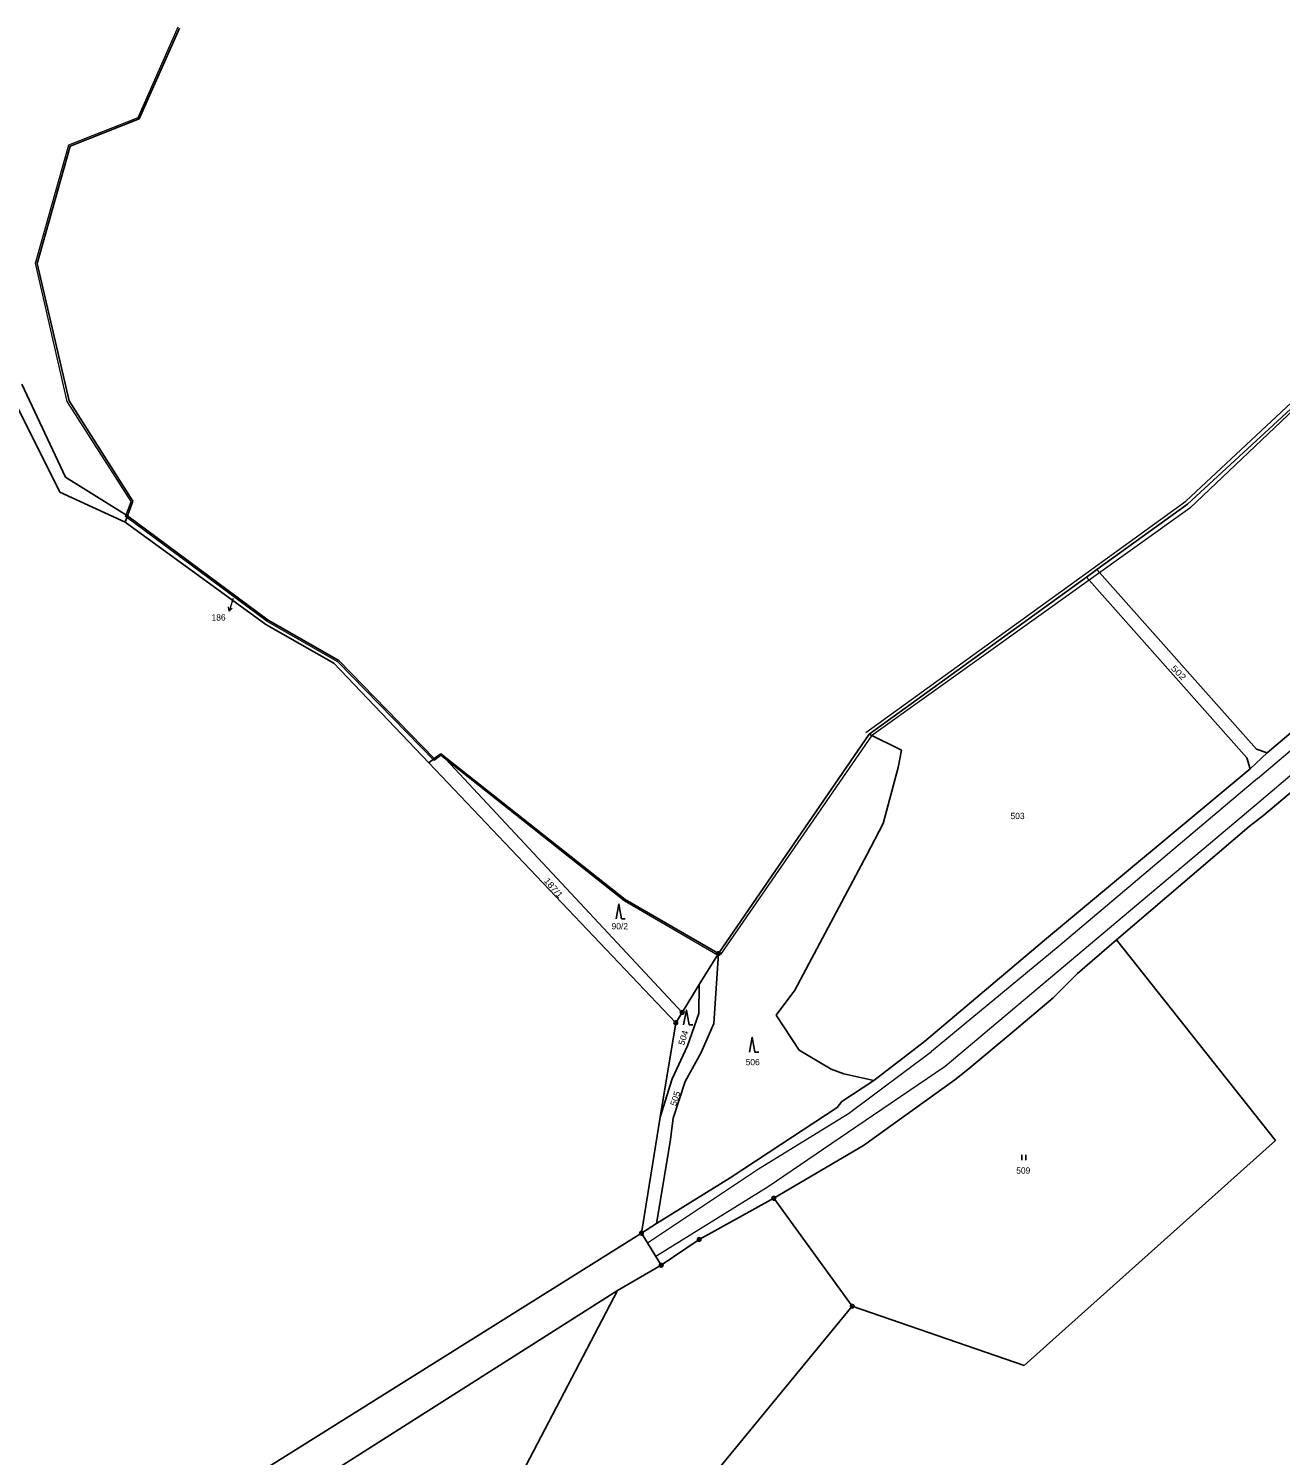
# Model space of a CAD drawing. Extents: x -653193 to -651624, y -1092017 to -1090260.
# Drawn here: x -652620.8 to -652283.1, y -1090861.4 to -1090476.3 of the extents above; entities that cross this region are included whole.
import ezdxf
from ezdxf.enums import TextEntityAlignment as Align

# ---------------------------------------------------------------- set-up
doc = ezdxf.new("R2010")
doc.units = 0
doc.header["$LTSCALE"] = 0.68
for name, color, linetype, lineweight in [('1', 7, 'Continuous', 25), ('3', 7, 'Continuous', 25), ('4', 7, 'Continuous', 13), ('7', 7, 'Continuous', 13), ('8', 7, 'Continuous', 25)]:
    doc.layers.add(name, color=color, linetype=linetype, lineweight=lineweight)
doc.layers.add('2', color=7, linetype='Continuous')

msp = doc.modelspace()

# ---------------------------------------------------------------- linework, layer by layer
at = {"layer": '1'}
for p, q in [((-652590.93, -1090500.73), (-652580.08, -1090476.22)), ((-652609.54, -1090508.04), (-652590.93, -1090500.73)), ((-652618.44, -1090539.69), (-652609.54, -1090508.04)), ((-652609.87, -1090576.8), (-652618.44, -1090539.69)), ((-652610.85, -1090597.36), (-652622.63, -1090572.26)), ((-652612.33, -1090601.42), (-652625.22, -1090575.6)), ((-652592.64, -1090603.89), (-652609.87, -1090576.8)), ((-652278.07, -1090576.84), (-652308.16, -1090604.7)), ((-652594.13, -1090607.87), (-652610.85, -1090597.36)), ((-652594.73, -1090609.56), (-652612.33, -1090601.42)), ((-652592.64, -1090603.89), (-652593.64, -1090606.57)), ((-652308.16, -1090604.7), (-652332.59, -1090622.35)), ((-652594.13, -1090607.87), (-652594.73, -1090609.56)), ((-652593.64, -1090606.57), (-652594.13, -1090607.87)), ((-652556.15, -1090635.96), (-652594.13, -1090607.87)), ((-652556.74, -1090637.15), (-652594.73, -1090609.56)), ((-652335.44, -1090624.41), (-652394.05, -1090666.77)), ((-652334.01, -1090623.38), (-652335.44, -1090624.41)), ((-652292.13, -1090673.13), (-652335.44, -1090624.41)), ((-652332.59, -1090622.35), (-652334.01, -1090623.38)), ((-652332.59, -1090622.35), (-652289.51, -1090670.8)), ((-652286.71, -1090671.78), (-652233.17, -1090626.65)), ((-652537.08, -1090646.85), (-652556.15, -1090635.96)), ((-652538.43, -1090647.58), (-652556.74, -1090637.15)), ((-652512.85, -1090674.5), (-652538.43, -1090647.58)), ((-652511.37, -1090673.36), (-652537.08, -1090646.85)), ((-652237.99, -1090646.81), (-652287.6, -1090688.58)), ((-652394.05, -1090666.77), (-652434.67, -1090725.95)), ((-652394.05, -1090666.77), (-652385.27, -1090671.07)), ((-652289.51, -1090670.8), (-652286.71, -1090671.78)), ((-652511.37, -1090673.36), (-652512.85, -1090674.5)), ((-652512.85, -1090674.5), (-652446.21, -1090744.64)), ((-652509.59, -1090672.03), (-652511.37, -1090673.36)), ((-652459.81, -1090711.37), (-652509.59, -1090672.03)), ((-652444.47, -1090741.83), (-652509.59, -1090672.03)), ((-652385.27, -1090671.07), (-652386.16, -1090675.71)), ((-652291.21, -1090676.12), (-652292.13, -1090673.13)), ((-652291.21, -1090676.12), (-652286.71, -1090671.78)), ((-652386.16, -1090675.71), (-652390.28, -1090690.83)), ((-652346.23, -1090721.9), (-652291.21, -1090676.12)), ((-652287.6, -1090688.58), (-652291.53, -1090691.65)), ((-652394.62, -1090699.31), (-652390.28, -1090690.83)), ((-652291.53, -1090691.65), (-652327.3, -1090722.23)), ((-652394.62, -1090699.31), (-652414.04, -1090735.86)), ((-652434.67, -1090725.95), (-652459.81, -1090711.37)), ((-652379.14, -1090749.72), (-652346.23, -1090721.9)), ((-652327.3, -1090722.23), (-652337.84, -1090731.35)), ((-652327.3, -1090722.23), (-652284.44, -1090776.42)), ((-652439.85, -1090734.34), (-652434.67, -1090725.95)), ((-652434.67, -1090725.95), (-652435.94, -1090744.83)), ((-652337.84, -1090731.35), (-652344.38, -1090737.91)), ((-652444.47, -1090741.83), (-652439.85, -1090734.34)), ((-652439.99, -1090742.13), (-652439.85, -1090734.34)), ((-652414.04, -1090735.86), (-652419.07, -1090742.55)), ((-652344.38, -1090737.91), (-652355.48, -1090747.23)), ((-652446.21, -1090744.64), (-652444.47, -1090741.83)), ((-652443.03, -1090750.89), (-652439.99, -1090742.13)), ((-652419.07, -1090742.55), (-652412.93, -1090752.06)), ((-652450.37, -1090770.15), (-652446.21, -1090744.64)), ((-652435.94, -1090744.83), (-652439.31, -1090752.66)), ((-652355.48, -1090747.23), (-652367.4, -1090757.27)), ((-652447.18, -1090759.75), (-652443.03, -1090750.89)), ((-652392.75, -1090760.24), (-652379.14, -1090749.72)), ((-652439.31, -1090752.66), (-652443.67, -1090760.48)), ((-652412.93, -1090752.06), (-652404.29, -1090757.12)), ((-652404.29, -1090757.12), (-652400.9, -1090758.45)), ((-652400.9, -1090758.45), (-652392.75, -1090760.24)), ((-652367.4, -1090757.27), (-652370.91, -1090760.03)), ((-652450.37, -1090770.15), (-652447.18, -1090759.75)), ((-652443.67, -1090760.48), (-652446.86, -1090770.38)), ((-652401.43, -1090765.9), (-652392.75, -1090760.24)), ((-652370.91, -1090760.03), (-652395.6, -1090777.78)), ((-652402.66, -1090767.49), (-652401.43, -1090765.9)), ((-652455.47, -1090801.44), (-652450.37, -1090770.15)), ((-652446.86, -1090770.38), (-652447.71, -1090776.73)), ((-652417.82, -1090777.48), (-652402.66, -1090767.49)), ((-652447.71, -1090776.73), (-652451.39, -1090798.77)), ((-652431.48, -1090786.52), (-652417.82, -1090777.48)), ((-652395.6, -1090777.78), (-652419.75, -1090792)), ((-652284.44, -1090776.42), (-652352.22, -1090837.11)), ((-652451.39, -1090798.77), (-652431.48, -1090786.52)), ((-652419.75, -1090792), (-652439.86, -1090803.1)), ((-652398.57, -1090821.14), (-652419.75, -1090792)), ((-652587.98, -1090884.44), (-652455.47, -1090801.44)), ((-652455.47, -1090801.44), (-652451.39, -1090798.77)), ((-652453.86, -1090804.03), (-652455.47, -1090801.44)), ((-652451.55, -1090807.75), (-652453.86, -1090804.03)), ((-652439.86, -1090803.1), (-652450.11, -1090810.08)), ((-652450.11, -1090810.08), (-652451.55, -1090807.75)), ((-652461.88, -1090816.92), (-652450.11, -1090810.08)), ((-652590.07, -1090898.28), (-652461.88, -1090816.92)), ((-652547.89, -1090980.88), (-652461.88, -1090816.92)), ((-652440.11, -1090871.57), (-652398.57, -1090821.14)), ((-652352.22, -1090837.11), (-652398.57, -1090821.14))]:
    msp.add_line(p, q, dxfattribs=at)
at = {"layer": '3'}
for p, q in [((-652460.8, -1090716.6), (-652459.804, -1090716.6)), ((-652442.58, -1090745.21), (-652441.584, -1090745.21)), ((-652424.83, -1090752.53), (-652423.834, -1090752.53)), ((-652352.801, -1090781.74), (-652352.801, -1090780.24)), ((-652351.8, -1090781.74), (-652351.8, -1090780.24))]:
    msp.add_line(p, q, dxfattribs=at)
for points in [[(-652460.8, -1090716.6), (-652461.55, -1090712.6), (-652462.3, -1090716.6)], [(-652442.58, -1090745.21), (-652443.33, -1090741.21), (-652444.08, -1090745.21)], [(-652424.83, -1090752.53), (-652425.58, -1090748.53), (-652426.33, -1090752.53)]]:
    msp.add_lwpolyline(points, dxfattribs=at)
at = {"layer": '4'}
for p, q in [((-652591.23, -1090500.33), (-652580.44, -1090475.87)), ((-652609.93, -1090507.73), (-652591.23, -1090500.33)), ((-652618.94, -1090539.65), (-652609.93, -1090507.73)), ((-652610.33, -1090576.99), (-652618.94, -1090539.65)), ((-652593.14, -1090603.92), (-652610.33, -1090576.99)), ((-652594.62, -1090607.97), (-652593.14, -1090603.92)), ((-652556.43, -1090636.38), (-652594.62, -1090607.97)), ((-652537.38, -1090647.25), (-652556.43, -1090636.38)), ((-652511.4, -1090673.86), (-652537.38, -1090647.25)), ((-652289.3, -1090678.68), (-652251.17, -1090646.33)), ((-652248.6, -1090650.75), (-652289.95, -1090686.08)), ((-652509.55, -1090672.53), (-652511.4, -1090673.86)), ((-652460.12, -1090711.76), (-652509.55, -1090672.53)), ((-652289.3, -1090678.68), (-652343.02, -1090724.16)), ((-652289.95, -1090686.08), (-652373.57, -1090756.39)), ((-652434.97, -1090726.35), (-652460.12, -1090711.76)), ((-652343.02, -1090724.16), (-652377.18, -1090752.38)), ((-652399.61, -1090769.08), (-652377.18, -1090752.38)), ((-652373.57, -1090756.39), (-652397.66, -1090772.84)), ((-652423.84, -1090784.07), (-652399.61, -1090769.08)), ((-652397.66, -1090772.84), (-652421.3, -1090788.94)), ((-652453.86, -1090804.03), (-652423.84, -1090784.07)), ((-652421.3, -1090788.94), (-652451.55, -1090807.75))]:
    msp.add_line(p, q, dxfattribs=at)
for points in [[(-652394.94, -1090666.29), (-652333.98, -1090622.23), (-652308.65, -1090603.85), (-652278.77, -1090575.95), (-652273.68, -1090571.31), (-652211.73, -1090525.03), (-652121.11, -1090476.43), (-652121.78, -1090487.72), (-652113.48, -1090504.55), (-652101.85, -1090521.87), (-652095.29, -1090531.68)], [(-651924.64, -1090810.59), (-651944.72, -1090786.79), (-651953.83, -1090771.34), (-651957.54, -1090759.26), (-651970.54, -1090744.66), (-651971.3, -1090737.57), (-651990.03, -1090683.62), (-652010.36, -1090668.34), (-652012.98, -1090658.29), (-652096.76, -1090532.33), (-652114.98, -1090505.23), (-652123.25, -1090488.26), (-652122.91, -1090478.89), (-652210.49, -1090526.59), (-652277.57, -1090577.33), (-652307.52, -1090605.78), (-652393.41, -1090667.24), (-652434.16, -1090726.25)]]:
    msp.add_lwpolyline(points, dxfattribs=at)
at = {"layer": '7'}
msp.add_line((-652566.637, -1090633.52), (-652565.866, -1090632.709), dxfattribs=at)
msp.add_lwpolyline([(-652565.6, -1090630.12), (-652565.76, -1090630.65), (-652566.637, -1090633.52), (-652566.823, -1090632.416)], dxfattribs=at)
at = {"layer": '8'}
for centre, radius in [((-652434.67, -1090725.9499), 0.5), ((-652434.67, -1090725.9499), 0.0303), ((-652446.21, -1090744.6399), 0.5), ((-652444.47, -1090741.8299), 0.5), ((-652444.47, -1090741.8299), 0.0303), ((-652446.21, -1090744.6399), 0.0303), ((-652419.75, -1090791.9999), 0.5), ((-652419.75, -1090791.9999), 0.0303), ((-652455.47, -1090801.4399), 0.5), ((-652455.47, -1090801.4399), 0.0303), ((-652439.86, -1090803.0999), 0.5), ((-652439.86, -1090803.0999), 0.0303), ((-652450.11, -1090810.0799), 0.5), ((-652450.11, -1090810.0799), 0.0303), ((-652398.57, -1090821.1399), 0.5), ((-652398.57, -1090821.1399), 0.0303)]:
    msp.add_circle(centre, radius, dxfattribs=at)

# ---------------------------------------------------------------- texts
at = {"layer": '2'}
msp.add_text('186', height=1.7, dxfattribs=at).set_placement((-652567.629, -1090636.085), align=Align.RIGHT)
for s, rotation, width, p in [('502', 315, 1.2, (-652311.1635, -1090650.7665)), ('187/1', 311, 1.1, (-652479.8135, -1090708.7624)), ('504', 72, 1.05, (-652443.3521, -1090748.9367)), ('505', 72, 1.05, (-652445.5221, -1090765.3267))]:
    msp.add_text(s, height=1.7, rotation=rotation, dxfattribs=dict(at, width=width)).set_placement(p, align=Align.CENTER)
for s, p in [('503', (-652353.999, -1090689.675)), ('90/2', (-652461.299, -1090719.435)), ('506', (-652425.449, -1090756.095)), ('509', (-652352.459, -1090785.355))]:
    msp.add_text(s, height=1.7, dxfattribs=at).set_placement(p, align=Align.CENTER)

doc.saveas('drawing.dxf')
